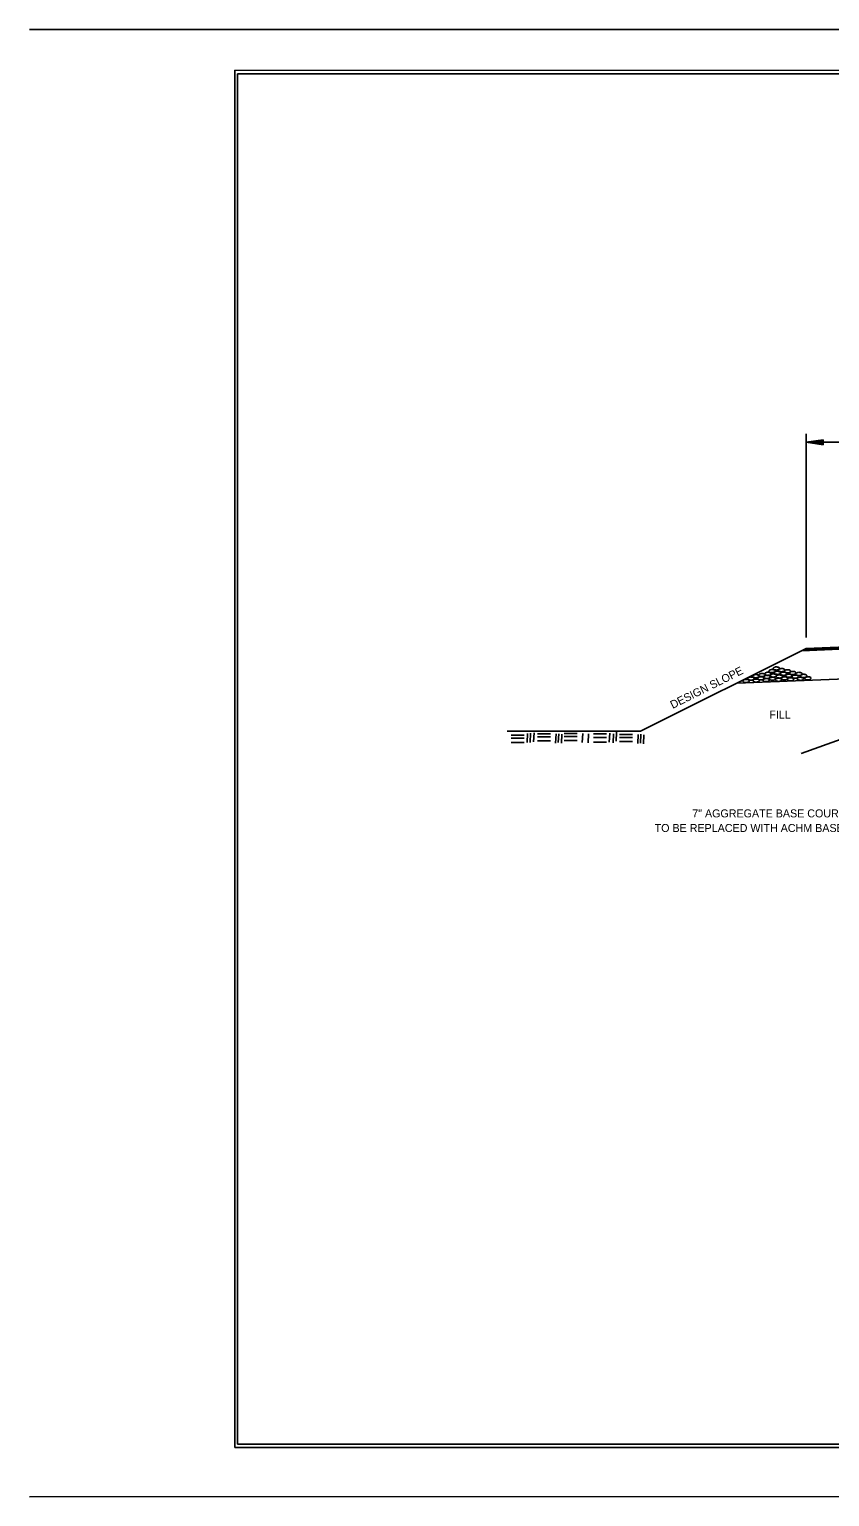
# Model space of a CAD drawing. Extents: x 714919 to 718439, y 1619644 to 1621844.
# Drawn here: x 714919 to 716119, y 1619644 to 1621844 of the extents above; entities that cross this region are included whole.
import ezdxf

# ---------------------------------------------------------------- set-up
doc = ezdxf.new("R2010")
doc.units = 0
for name, color, linetype in [('R_Annotation', 7, 'Continuous'), ('R_Border', 7, 'Continuous'), ('R_Dimension', 7, 'Continuous'), ('R_Draft', 7, 'Continuous'), ('R_No Plot', 7, 'Continuous')]:
    doc.layers.add(name, color=color, linetype=linetype)

msp = doc.modelspace()

# ---------------------------------------------------------------- linework, layer by layer
at = {"layer": 'R_Border'}
for p, q in [((718439, 1621843.8), (714919, 1621843.5)), ((715231.2, 1619722.5), (715231.3, 1621777.1)), ((715231.3, 1621777.1), (718393.1, 1621777.1)), ((718393.2, 1619722.5), (715231.2, 1619722.5)), ((714919.1, 1619643.5), (718439.3, 1619643.8))]:
    msp.add_line(p, q, dxfattribs=at)
at = {"layer": 'R_Dimension'}
for p, q in [((716083.9, 1620931.6), (716083.9, 1621237.2)), ((716109.1, 1621228.4), (716083.9, 1621224.6)), ((716109.1, 1621227.8), (716088.1, 1621224.6)), ((716109.1, 1621227.2), (716092.4, 1621224.6)), ((716109.1, 1621226.5), (716096.6, 1621224.6)), ((716109.1, 1621225.9), (716100.9, 1621224.6)), ((716109.1, 1621220.9), (716109.1, 1621228.4)), ((716083.9, 1621224.6), (717366, 1621224.6)), ((716109.1, 1621220.9), (716083.9, 1621224.6)), ((716109.1, 1621221.5), (716088.1, 1621224.6)), ((716109.1, 1621222.2), (716092.4, 1621224.6)), ((716109.1, 1621222.8), (716096.6, 1621224.6)), ((716109.1, 1621223.5), (716100.9, 1621224.6)), ((716109.1, 1621225.2), (716105.1, 1621224.6)), ((716109.1, 1621224), (716105.1, 1621224.6))]:
    msp.add_line(p, q, dxfattribs=at)
at = {"layer": 'R_Draft'}
for p, q in [((716077.3, 1620912), (717371.8, 1620963.7)), ((716079, 1620912.9), (717370.4, 1620964.4)), ((716080.7, 1620913.7), (717369, 1620965.1)), ((716082.4, 1620914.6), (717367.5, 1620965.9)), ((716083.9, 1620915.3), (717366.1, 1620966.5)), ((715835.5, 1620791.2), (716083.9, 1620915.3)), ((715980.2, 1620863.5), (716482.5, 1620883.5)), ((716371.5, 1620863.6), (716076.2, 1620758.1)), ((715635.3, 1620791.2), (715835.5, 1620791.2)), ((715666.1, 1620787.9), (715665.3, 1620774.4)), ((715670.7, 1620788.2), (715670, 1620774.6)), ((715676, 1620788.7), (715675.1, 1620775.2)), ((715680.9, 1620787.2), (715700.5, 1620787.2)), ((715708.7, 1620787.2), (715708, 1620773.6)), ((715712.8, 1620787.6), (715712, 1620774.2)), ((715717.4, 1620786.7), (715716.7, 1620773.2)), ((715721, 1620787.8), (715740.6, 1620787.8)), ((715748.8, 1620787.8), (715748.1, 1620774.3)), ((715757.5, 1620787.3), (715756.8, 1620773.8)), ((715764.8, 1620787.5), (715784.4, 1620787.5)), ((715789.3, 1620788.6), (715788.4, 1620775)), ((715795, 1620787.4), (715794.3, 1620773.9)), ((715799.6, 1620789.8), (715798.8, 1620776.2)), ((715804, 1620786.3), (715823.6, 1620786.3)), ((715831.9, 1620786.3), (715831.2, 1620772.8)), ((715836, 1620786.8), (715835.2, 1620773.2)), ((715840.6, 1620785.8), (715839.8, 1620772.3)), ((715641.4, 1620785.2), (715660.9, 1620785.2)), ((715641.4, 1620780.7), (715660.9, 1620780.7)), ((715641.4, 1620774.6), (715660.9, 1620774.6)), ((715680.9, 1620782.7), (715700.5, 1620782.7)), ((715680.9, 1620776.7), (715700.5, 1620776.7)), ((715721, 1620783.3), (715740.6, 1620783.3)), ((715721, 1620777.2), (715740.6, 1620777.2)), ((715764.8, 1620781.7), (715784.4, 1620781.7)), ((715764.8, 1620774.7), (715784.4, 1620774.7)), ((715804, 1620781.8), (715823.6, 1620781.8)), ((715804, 1620775.8), (715823.6, 1620775.8))]:
    msp.add_line(p, q, dxfattribs=at)
for points in [[(716008.3, 1620876.2), (716010, 1620876.2), (716011.9, 1620875.5), (716012.9, 1620874.6), (716013.1, 1620874.1), (716012.5, 1620873), (716012, 1620872.5), (716010.9, 1620872), (716009.3, 1620871.6), (716008.5, 1620871.5), (716007.2, 1620871.6), (716005.8, 1620871.8), (716004.8, 1620872.3), (716003.8, 1620873.1), (716003.6, 1620873.7), (716003.9, 1620874.6), (716004.7, 1620875.3), (716005.4, 1620875.6), (716006.6, 1620876), (716007.2, 1620876.2), (716008.3, 1620876.2)], [(716017.5, 1620877.9), (716019.2, 1620877.8), (716021.1, 1620877.2), (716022.1, 1620876.3), (716022.2, 1620875.7), (716021.7, 1620874.7), (716021.2, 1620874.2), (716020.1, 1620873.7), (716018.5, 1620873.2), (716017.7, 1620873.2), (716016.4, 1620873.4), (716015.1, 1620873.5), (716014, 1620873.9), (716013, 1620874.8), (716012.8, 1620875.4), (716013.1, 1620876.3), (716013.9, 1620876.9), (716014.6, 1620877.3), (716015.8, 1620877.7), (716016.4, 1620877.9), (716017.5, 1620877.9)], [(716025.2, 1620875.1), (716026.8, 1620875), (716028.8, 1620874.4), (716029.8, 1620873.5), (716029.9, 1620872.9), (716029.4, 1620871.9), (716028.9, 1620871.4), (716027.8, 1620870.9), (716026.2, 1620870.4), (716025.3, 1620870.4), (716024.1, 1620870.5), (716022.7, 1620870.7), (716021.7, 1620871.1), (716020.6, 1620872), (716020.5, 1620872.6), (716020.8, 1620873.5), (716021.6, 1620874.1), (716022.3, 1620874.5), (716023.4, 1620874.9), (716024.1, 1620875.1), (716025.2, 1620875.1)], [(716026.4, 1620879.9), (716028.1, 1620879.7), (716030, 1620879.1), (716031.1, 1620878.3), (716031.2, 1620877.7), (716030.7, 1620876.7), (716030.1, 1620876.1), (716029.1, 1620875.5), (716027.5, 1620875.2), (716026.6, 1620875.2), (716025.4, 1620875.1), (716024, 1620875.4), (716022.9, 1620875.9), (716021.9, 1620876.8), (716021.8, 1620877.3), (716022.1, 1620878.3), (716022.8, 1620878.9), (716023.6, 1620879.2), (716024.7, 1620879.6), (716025.4, 1620879.8), (716026.4, 1620879.9)], [(716032.6, 1620883.9), (716034.3, 1620883.7), (716036.2, 1620883.2), (716037.3, 1620882.3), (716037.5, 1620881.7), (716036.9, 1620880.7), (716036.3, 1620880.3), (716035.2, 1620879.7), (716033.6, 1620879.2), (716032.8, 1620879.2), (716031.6, 1620879.4), (716030.1, 1620879.4), (716029.1, 1620879.9), (716028.2, 1620880.8), (716028, 1620881.4), (716028.3, 1620882.3), (716029.1, 1620883), (716029.8, 1620883.3), (716030.9, 1620883.6), (716031.6, 1620883.9), (716032.6, 1620883.9)], [(716034.5, 1620877.3), (716036.2, 1620877.1), (716038.2, 1620876.5), (716039.2, 1620875.6), (716039.4, 1620875.1), (716038.9, 1620874), (716038.3, 1620873.6), (716037.1, 1620872.9), (716035.6, 1620872.6), (716034.7, 1620872.6), (716033.5, 1620872.6), (716032.1, 1620872.8), (716031.1, 1620873.3), (716030.1, 1620874.1), (716029.9, 1620874.8), (716030.3, 1620875.7), (716031, 1620876.3), (716031.7, 1620876.6), (716032.8, 1620877), (716033.5, 1620877.2), (716034.5, 1620877.3)], [(716038.9, 1620887.8), (716040.6, 1620887.6), (716042.6, 1620887.1), (716043.6, 1620886.2), (716043.8, 1620885.6), (716043.3, 1620884.6), (716042.6, 1620884.1), (716041.5, 1620883.5), (716039.9, 1620883.1), (716039.1, 1620883.1), (716037.9, 1620883.2), (716036.5, 1620883.3), (716035.5, 1620883.7), (716034.5, 1620884.6), (716034.4, 1620885.2), (716034.6, 1620886.2), (716035.4, 1620886.8), (716036.1, 1620887.1), (716037.2, 1620887.5), (716037.8, 1620887.8), (716038.9, 1620887.8)], [(716040.6, 1620881.3), (716042.3, 1620881.1), (716044.3, 1620880.6), (716045.3, 1620879.7), (716045.4, 1620879.1), (716044.9, 1620878.1), (716044.3, 1620877.6), (716043.3, 1620877), (716041.7, 1620876.6), (716040.8, 1620876.6), (716039.6, 1620876.8), (716038.2, 1620876.8), (716037.2, 1620877.3), (716036.2, 1620878.2), (716036, 1620878.8), (716036.3, 1620879.7), (716037.1, 1620880.3), (716037.8, 1620880.6), (716038.9, 1620881.1), (716039.6, 1620881.3), (716040.6, 1620881.3)], [(716043.6, 1620875.9), (716045.2, 1620875.6), (716047.2, 1620875.1), (716048.2, 1620874.2), (716048.3, 1620873.6), (716047.8, 1620872.6), (716047.3, 1620872.1), (716046.2, 1620871.5), (716044.6, 1620871.1), (716043.7, 1620871.1), (716042.5, 1620871.2), (716041.1, 1620871.3), (716040, 1620871.8), (716039, 1620872.7), (716038.9, 1620873.3), (716039.2, 1620874.2), (716039.9, 1620874.8), (716040.7, 1620875.2), (716041.9, 1620875.6), (716042.5, 1620875.8), (716043.6, 1620875.9)], [(716046.9, 1620885.3), (716048.6, 1620885.2), (716050.6, 1620884.5), (716051.6, 1620883.7), (716051.7, 1620883.2), (716051.2, 1620882.1), (716050.7, 1620881.6), (716049.6, 1620881), (716048, 1620880.7), (716047.2, 1620880.6), (716045.9, 1620880.6), (716044.5, 1620880.9), (716043.5, 1620881.4), (716042.5, 1620882.1), (716042.3, 1620882.8), (716042.6, 1620883.7), (716043.4, 1620884.4), (716044.1, 1620884.7), (716045.2, 1620885), (716045.9, 1620885.2), (716046.9, 1620885.3)], [(716049.7, 1620879.8), (716051.4, 1620879.8), (716053.4, 1620879.2), (716054.4, 1620878.2), (716054.5, 1620877.6), (716054, 1620876.6), (716053.5, 1620876.2), (716052.3, 1620875.6), (716050.8, 1620875.1), (716049.9, 1620875.1), (716048.7, 1620875.2), (716047.3, 1620875.5), (716046.3, 1620875.8), (716045.2, 1620876.7), (716045.1, 1620877.3), (716045.4, 1620878.3), (716046.2, 1620878.8), (716046.9, 1620879.2), (716048, 1620879.7), (716048.7, 1620879.8), (716049.7, 1620879.8)], [(716055.8, 1620883.6), (716057.4, 1620883.5), (716059.5, 1620882.9), (716060.4, 1620881.9), (716060.6, 1620881.4), (716060, 1620880.3), (716059.5, 1620879.9), (716058.4, 1620879.4), (716056.8, 1620878.9), (716055.9, 1620878.9), (716054.7, 1620879), (716053.3, 1620879.2), (716052.3, 1620879.6), (716051.3, 1620880.4), (716051.1, 1620881), (716051.4, 1620882), (716052.2, 1620882.5), (716052.9, 1620883.1), (716054, 1620883.4), (716054.7, 1620883.5), (716055.8, 1620883.6)], [(716057.8, 1620876.9), (716059.5, 1620876.8), (716061.4, 1620876.2), (716062.4, 1620875.3), (716062.5, 1620874.7), (716062, 1620873.6), (716061.5, 1620873.2), (716060.4, 1620872.6), (716058.8, 1620872.2), (716058, 1620872.2), (716056.7, 1620872.2), (716055.3, 1620872.4), (716054.3, 1620872.9), (716053.2, 1620873.7), (716053.1, 1620874.4), (716053.4, 1620875.3), (716054.1, 1620875.9), (716054.9, 1620876.2), (716056, 1620876.6), (716056.8, 1620876.8), (716057.8, 1620876.9)], [(716063.7, 1620881), (716065.4, 1620880.9), (716067.3, 1620880.3), (716068.3, 1620879.4), (716068.5, 1620878.8), (716067.9, 1620877.8), (716067.5, 1620877.3), (716066.3, 1620876.8), (716064.7, 1620876.3), (716063.9, 1620876.3), (716062.6, 1620876.4), (716061.3, 1620876.6), (716060.2, 1620877), (716059.1, 1620877.9), (716059, 1620878.5), (716059.3, 1620879.4), (716060.1, 1620880), (716060.8, 1620880.4), (716061.9, 1620880.8), (716062.6, 1620881), (716063.7, 1620881)], [(716067.3, 1620875.5), (716069, 1620875.4), (716070.9, 1620874.8), (716071.9, 1620873.9), (716072.1, 1620873.4), (716071.6, 1620872.3), (716071.1, 1620871.8), (716069.9, 1620871.2), (716068.3, 1620870.9), (716067.5, 1620870.8), (716066.3, 1620870.8), (716064.8, 1620871.1), (716063.8, 1620871.6), (716062.8, 1620872.3), (716062.6, 1620873), (716063, 1620873.9), (716063.7, 1620874.6), (716064.5, 1620874.9), (716065.6, 1620875.3), (716066.2, 1620875.4), (716067.3, 1620875.5)], [(716072.9, 1620879.6), (716074.6, 1620879.6), (716076.5, 1620878.9), (716077.5, 1620878), (716077.7, 1620877.4), (716077.2, 1620876.3), (716076.6, 1620875.9), (716075.6, 1620875.4), (716073.9, 1620874.9), (716073.1, 1620874.9), (716071.9, 1620875), (716070.5, 1620875.2), (716069.4, 1620875.6), (716068.4, 1620876.4), (716068.2, 1620877.1), (716068.6, 1620878), (716069.3, 1620878.6), (716070.1, 1620879.1), (716071.2, 1620879.4), (716071.9, 1620879.6), (716072.9, 1620879.6)], [(716080.1, 1620876.7), (716081.7, 1620876.5), (716083.6, 1620875.9), (716084.6, 1620875), (716084.7, 1620874.5), (716084.3, 1620873.4), (716083.8, 1620872.9), (716082.6, 1620872.3), (716081, 1620872), (716080.2, 1620872), (716079, 1620872), (716077.6, 1620872.1), (716076.5, 1620872.7), (716075.5, 1620873.5), (716075.3, 1620874.1), (716075.6, 1620875.1), (716076.4, 1620875.7), (716077.1, 1620876), (716078.2, 1620876.3), (716079, 1620876.6), (716080.1, 1620876.7)], [(715993.7, 1620869), (715995.4, 1620868.9), (715997.3, 1620868.3), (715998.3, 1620867.4), (715998.5, 1620866.8), (715998, 1620865.8), (715997.5, 1620865.4), (715996.3, 1620864.8), (715994.7, 1620864.3), (715993.9, 1620864.3), (715992.6, 1620864.4), (715991.3, 1620864.6), (715990.2, 1620865), (715989.2, 1620865.8), (715989, 1620866.5), (715989.4, 1620867.4), (715990.1, 1620868), (715990.8, 1620868.5), (715992, 1620868.8), (715992.6, 1620869), (715993.7, 1620869)], [(716001.1, 1620872.6), (716002.7, 1620872.5), (716004.7, 1620871.9), (716005.7, 1620870.9), (716005.8, 1620870.4), (716005.3, 1620869.3), (716004.8, 1620868.9), (716003.7, 1620868.4), (716002.1, 1620867.9), (716001.3, 1620867.9), (716000, 1620868), (715998.6, 1620868.2), (715997.6, 1620868.6), (715996.6, 1620869.4), (715996.4, 1620870.1), (715996.7, 1620871), (715997.5, 1620871.6), (715998.2, 1620872), (715999.3, 1620872.4), (716000, 1620872.6), (716001.1, 1620872.6)], [(716008.9, 1620869.6), (716010.5, 1620869.5), (716012.5, 1620868.8), (716013.4, 1620868), (716013.6, 1620867.4), (716013.1, 1620866.3), (716012.6, 1620865.8), (716011.5, 1620865.4), (716009.9, 1620864.9), (716009, 1620864.8), (716007.8, 1620865), (716006.4, 1620865.2), (716005.3, 1620865.7), (716004.3, 1620866.4), (716004.2, 1620867.1), (716004.5, 1620867.9), (716005.2, 1620868.6), (716006, 1620869), (716007.1, 1620869.4), (716007.8, 1620869.5), (716008.9, 1620869.6)], [(716015.8, 1620873.1), (716017.5, 1620872.9), (716019.4, 1620872.3), (716020.4, 1620871.4), (716020.5, 1620870.8), (716020, 1620869.8), (716019.5, 1620869.3), (716018.4, 1620868.7), (716016.8, 1620868.4), (716015.9, 1620868.4), (716014.7, 1620868.4), (716013.3, 1620868.5), (716012.2, 1620869), (716011.2, 1620869.9), (716011.1, 1620870.6), (716011.4, 1620871.5), (716012.1, 1620872.1), (716012.9, 1620872.4), (716014, 1620872.7), (716014.7, 1620873), (716015.8, 1620873.1)], [(716023.9, 1620870.3), (716025.6, 1620870.2), (716027.6, 1620869.5), (716028.6, 1620868.7), (716028.7, 1620868.2), (716028.2, 1620867.1), (716027.7, 1620866.5), (716026.5, 1620865.9), (716025, 1620865.7), (716024.1, 1620865.6), (716022.9, 1620865.7), (716021.5, 1620865.8), (716020.5, 1620866.3), (716019.4, 1620867.1), (716019.3, 1620867.8), (716019.6, 1620868.7), (716020.3, 1620869.3), (716021.1, 1620869.7), (716022.2, 1620870), (716022.9, 1620870.2), (716023.9, 1620870.3)], [(716033.3, 1620872.4), (716035, 1620872.2), (716036.9, 1620871.6), (716037.9, 1620870.7), (716038, 1620870.2), (716037.6, 1620869.2), (716037.1, 1620868.6), (716035.9, 1620868), (716034.3, 1620867.7), (716033.5, 1620867.7), (716032.2, 1620867.7), (716030.9, 1620867.9), (716029.8, 1620868.4), (716028.8, 1620869.2), (716028.6, 1620869.9), (716028.9, 1620870.8), (716029.7, 1620871.4), (716030.4, 1620871.7), (716031.6, 1620872.1), (716032.3, 1620872.3), (716033.3, 1620872.4)], [(716042.4, 1620870.8), (716044, 1620870.7), (716046, 1620870.1), (716046.9, 1620869.2), (716047.1, 1620868.6), (716046.6, 1620867.5), (716046.1, 1620867.1), (716045, 1620866.6), (716043.4, 1620866.1), (716042.5, 1620866), (716041.3, 1620866.2), (716039.9, 1620866.4), (716038.8, 1620866.9), (716037.8, 1620867.6), (716037.7, 1620868.3), (716038, 1620869.2), (716038.8, 1620869.9), (716039.5, 1620870.3), (716040.6, 1620870.6), (716041.3, 1620870.7), (716042.4, 1620870.8)], [(716051.4, 1620873), (716053.1, 1620872.8), (716055.1, 1620872.2), (716056, 1620871.3), (716056.2, 1620870.7), (716055.6, 1620869.7), (716055.2, 1620869.2), (716054, 1620868.7), (716052.5, 1620868.2), (716051.6, 1620868.2), (716050.3, 1620868.4), (716049, 1620868.5), (716047.9, 1620868.9), (716046.9, 1620869.8), (716046.7, 1620870.4), (716047, 1620871.3), (716047.8, 1620871.9), (716048.6, 1620872.3), (716049.7, 1620872.7), (716050.3, 1620872.9), (716051.4, 1620873)], [(716060.3, 1620871.6), (716062, 1620871.5), (716064, 1620870.9), (716065, 1620870), (716065.2, 1620869.4), (716064.6, 1620868.4), (716064.2, 1620867.9), (716063, 1620867.4), (716061.4, 1620866.9), (716060.6, 1620866.9), (716059.3, 1620867), (716057.9, 1620867.2), (716056.9, 1620867.6), (716055.9, 1620868.5), (716055.7, 1620869.1), (716056, 1620870), (716056.8, 1620870.6), (716057.5, 1620871), (716058.6, 1620871.5), (716059.3, 1620871.6), (716060.3, 1620871.6)], [(716075, 1620872.3), (716076.8, 1620872.1), (716078.7, 1620871.6), (716079.8, 1620870.7), (716079.9, 1620870.1), (716079.4, 1620869.1), (716078.9, 1620868.6), (716077.7, 1620868), (716076.1, 1620867.6), (716075.3, 1620867.6), (716074, 1620867.7), (716072.6, 1620867.8), (716071.6, 1620868.3), (716070.6, 1620869.2), (716070.5, 1620869.8), (716070.8, 1620870.7), (716071.5, 1620871.3), (716072.2, 1620871.7), (716073.4, 1620872.1), (716074, 1620872.3), (716075, 1620872.3)], [(716086.4, 1620872.9), (716088.1, 1620872.9), (716090, 1620872.2), (716091, 1620871.3), (716091.1, 1620870.7), (716090.7, 1620869.7), (716090.1, 1620869.2), (716089.1, 1620868.7), (716087.4, 1620868.3), (716086.6, 1620868.2), (716085.4, 1620868.3), (716083.9, 1620868.5), (716082.9, 1620868.9), (716081.9, 1620869.8), (716081.7, 1620870.4), (716082, 1620871.3), (716082.8, 1620872), (716083.5, 1620872.4), (716084.7, 1620872.7), (716085.4, 1620872.9), (716086.4, 1620872.9)]]:
    msp.add_spline(points, degree=3, dxfattribs=at)
at = {"layer": 'R_No Plot'}
msp.add_lwpolyline([(715227.2, 1619717.3), (718397.1, 1619717.4), (718397.2, 1621782.5), (715227.1, 1621782.3)], close=True, dxfattribs=at)

# ---------------------------------------------------------------- texts
at = {"layer": 'R_Annotation'}
msp.add_text('DESIGN SLOPE', height=12, rotation=26.565, dxfattribs=at).set_placement((715883.7, 1620824.7))
for s, p in [('FILL', (716028.6, 1620810.3)), ('7" AGGREGATE BASE COURSE (CLASS 7)', (715913, 1620662.1)), ('TO BE REPLACED WITH ACHM BASE COURSE (1-', (715856.6, 1620640.2))]:
    msp.add_text(s, height=12, dxfattribs=at).set_placement(p)

doc.saveas('drawing.dxf')
